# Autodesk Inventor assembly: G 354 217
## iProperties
Company: Mayer & Müller AG Schaltgeräte
Created: 2006-07
Part Number: G 354 217
Document SubType Name: Assembly
Designer: I.Baliuc
Manufacturer: Standard
Standards Organization: Custom
Description: Schalthebel, kompl.
Mass: 905.604 g
Surface Area: 400.654 cm^2
Volume: 115.185 cm^3
Density: 7.86217 g/cm^3
Author: T.Messerschmitt
Revision Number: 354217
Comments: änlich wie G 354 202 - nur ohne Spitze
